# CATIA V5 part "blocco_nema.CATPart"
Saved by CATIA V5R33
Part number: blocco_nema
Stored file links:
  C:\Users\Ryzen5700u\Desktop\robot_cicloidale_singolo\Assieme_robot_cicloidale_singolo\blocco_nema.CATPart

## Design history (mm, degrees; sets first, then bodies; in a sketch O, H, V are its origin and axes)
Body1 "Solido1" (main body)
  Solid1: solid without history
